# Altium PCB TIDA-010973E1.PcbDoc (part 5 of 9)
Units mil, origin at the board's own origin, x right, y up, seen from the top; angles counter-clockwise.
Board outline 5166 x 3669 mil, 8 copper layers (L01 - TOP, L02 - GND, L03 - SIG, L04 - GND, L05 - PWR, L06 - SIG, L07 - GND, L08 - BOTTOM), stack 61.7 mil thick; 677 components, 493 nets, 2522 pads, 1424 vias.
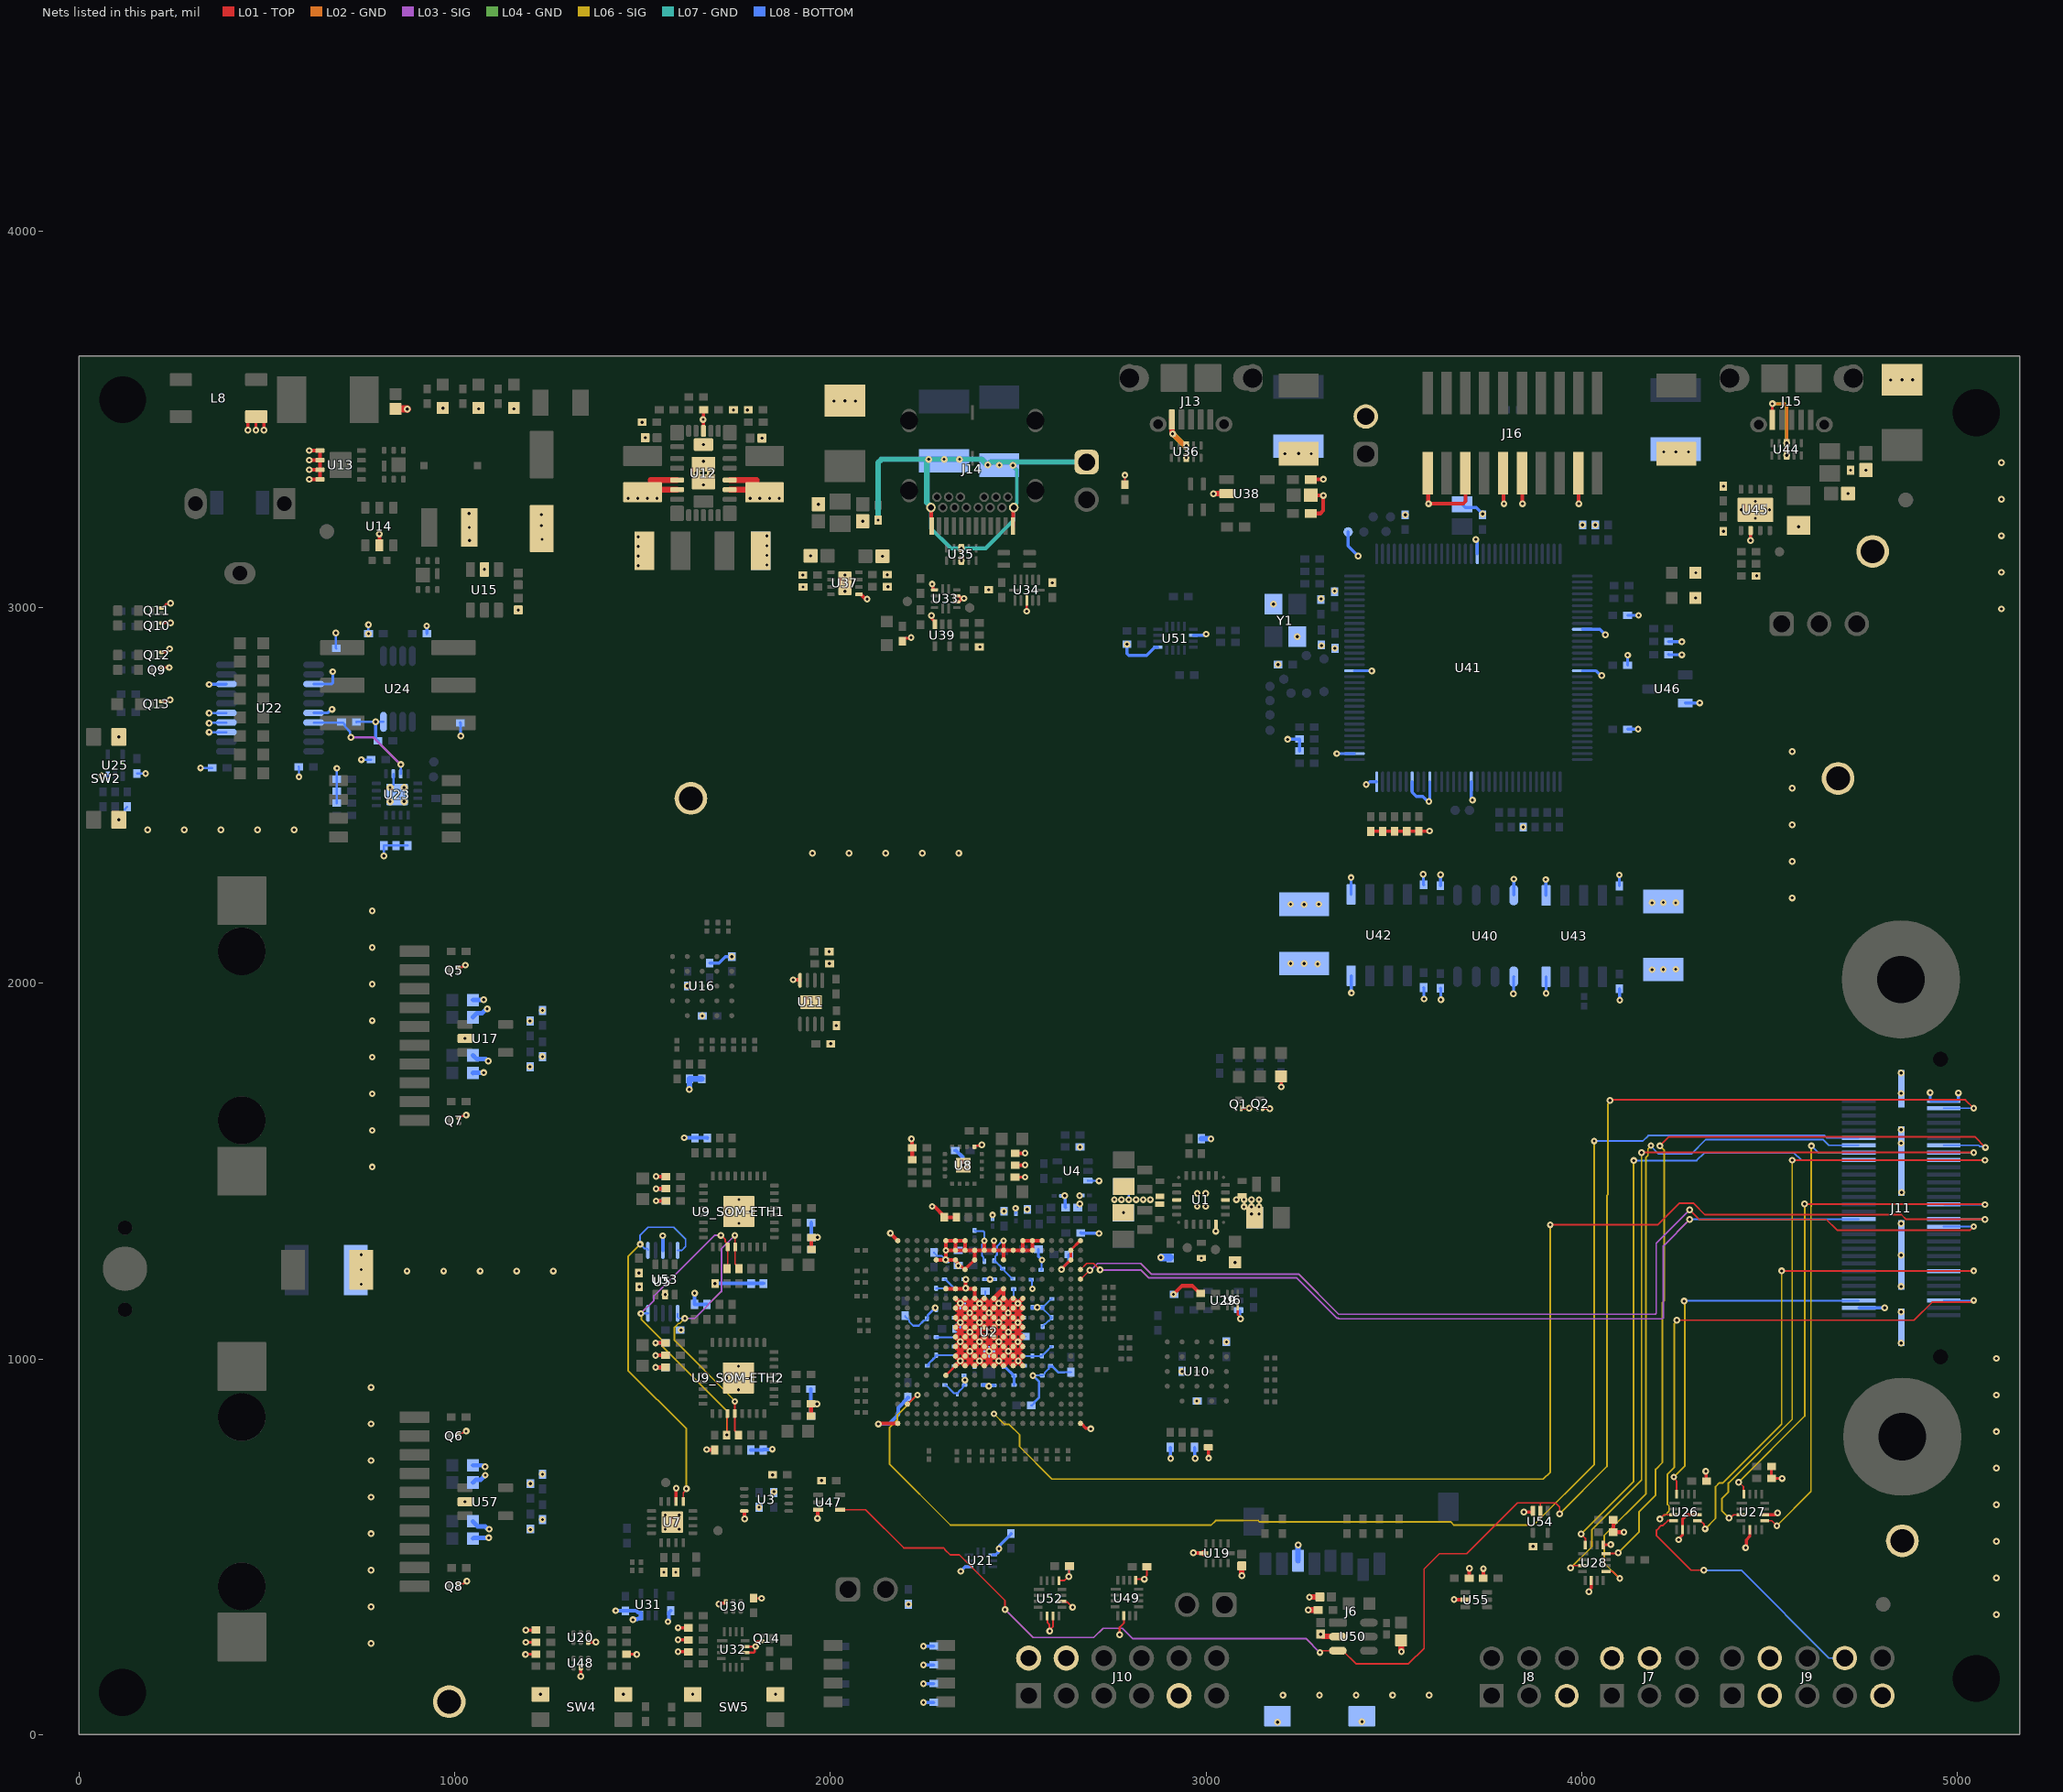
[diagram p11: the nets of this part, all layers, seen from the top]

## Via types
v1: diameter 18, hole 8, L01 - TOP to L08 - BOTTOM, tented both sides, 1389 vias
v2: diameter 19.68, hole 7.87, L01 - TOP to L08 - BOTTOM, 24 vias
v3: diameter 19.68, hole 7.87, L01 - TOP to L08 - BOTTOM, tented both sides, 11 vias

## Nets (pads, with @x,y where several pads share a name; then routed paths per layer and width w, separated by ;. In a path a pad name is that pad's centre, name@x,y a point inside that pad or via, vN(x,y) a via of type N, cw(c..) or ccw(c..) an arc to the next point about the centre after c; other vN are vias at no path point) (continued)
FSITX0_DATA1: J9.8 U26.4 | length 707.4
  L01 - TOP w4.5: U26.4@4244.5,569.38 4243.69,570.19 4229.25,570.19 4216.23,557.17 4211.77,557.17 4198.75,544.15 4198.75,529.85 4290.6,438 v1(4325,438)
  L08 - BOTTOM w4.5: v1(4325,438) 4325.5,437.5 4424.1,437.5 4657.6,204 J9.8@4700,204
GND: C1.1 C2.1 C3.1 C4.1 C5.1 C6.1 C7.1 C8.1 C9.1 C10.1 C11.1 C12.1 C13.1 C14.2 C15.2 C16.2 C17.1 C18.1 C19.1 C20.2 C21.2 C22.2 C23.2 C24.2 C25.2 C26.2 C27.1 C28.1 C29.1 C30.1 C31.1 C32.1 C33.1 C34.1 C35.2 C36.2 C37.2 C38.2 C39.2 C40.1 C41.1 C42.1 C43.2 C44.2 C45.1 C48.1 C49.2 C50.2 C51.2 C52.1 C53.1 C54.1 C55.1 C56.2 C57.2 C58.2 C59.1 C60.1 C61.2 C62.1 C63.2 C64.2 C65.2 C66.2 C67.2 C68.1 C69_SOM-ETH1.2 C69_SOM-ETH2.2 C70_SOM-ETH1.2 C70_SOM-ETH2.2 C71_SOM-ETH1.2 C71_SOM-ETH2.2 C72_SOM-ETH1.2 C72_SOM-ETH2.2 C73_SOM-ETH1.2 C73_SOM-ETH2.2 C74_SOM-ETH1.2 C74_SOM-ETH2.2 C75_SOM-ETH1.2 C75_SOM-ETH2.2 C76_SOM-ETH1.2 C76_SOM-ETH2.2 C77_SOM-ETH1.2 C77_SOM-ETH2.2 C78_SOM-ETH1.2 C78_SOM-ETH2.2 C79_SOM-ETH1.2 C79_SOM-ETH2.2 C80_SOM-ETH1.2 C80_SOM-ETH2.2 C81_SOM-ETH1.1 C81_SOM-ETH2.1 C82.2 C83.2 C84.2 C85.1 C86.2 C87.2 C88.1 C89.1 C90.1 C91.2 C92.1 C93.1 C94.1 C95.1 C96.2 C97.2 C100.2 C102.2 C103.2 C104.2 C105.2 C106.2 C107.2 C108.2 C109.2 C110.2 C111.2 C112.2 C113.2 C114.2 C115.2 C116.1 C117.2 C118.2 C119.2 C120.1 C121.1 C122.2 C123.1 C124.2 C125.1 C126.1 C127.2 C128.2 C129.2 C130.1 C131.1 C132.2 C133.2 C134.1 C135.1 C136.2 C137.2 C138.1 C145.2 C146.2 C147.2 C151.2 C172.1 C173.1 C174.1 C175.2 C176.1 C177.2 C178.2 C179.1 C180.2 C181.1 C182.2 C183.2 C184.2 C185.2 C186.2 C187.2 C188.2 C189.2 C190.1 C191_SOM-ETH1.2 C191_SOM-ETH2.2 C192.1 C193.1 C194.2 C195.2 C196.2 C197.2 C198.1 C199.1 C200.1 C201.1 C202.1 C203.1 C204.1 C205.1 C206.2 C207.1 C208.1 C209.2 C210.1 C211.1 C212.2 C213.1 C214.2 C215.1 C216.2 C217.1 C218.1 C219.2 D1.1 D4.1 D5.1 D6.1 D18.1 J6.6 J6.10 J7.2 J7.4 J8.5 J9.3 J9.4 J9.9 J10.2 J10.4 J10.9 J11.3 J11.60 J11.MP1 J11.MP2 J11.MP3 J11.MP4 J13.5 J14.A1 J14.A12 J14.B1 J14.B12 J16.4 J16.10 J16.12 J16.16 J16.20 J17.2 J20.1 L8.3 Q1.2 Q2.2 Q5.2 Q6.2 Q7.2 Q8.2 Q9.2 Q10.2 Q11.2 Q12.2 Q13.2 Q14.2 R2.1 R6.2 R14.2 R21.1 R25_SOM-ETH1.1 R25_SOM-ETH2.1 R26_SOM-ETH1.1 R26_SOM-ETH2.1 R28_SOM-ETH1.2 R28_SOM-ETH2.2 R51.1 R52.1 R56.1 R57.1 R59.1 R61.1 R62.1 R88.1 R93.1 R95.1 R96.1 R103.1 R108.2 R109.2 R110.2 R111.2 R114.1 R115.1 R116.1 R117.1 R118.1 R119.1 R128.1 R129.1 R130.1 R131.1 R132.1 R134.2 R139.1 R140.1 R142.2 R143.1 R144.2 R162.1 R169.1 R180.1 R181.2 R190.1 R191.1 R195.2 R197.2 R199.2 R200.2 R204_SOM-ETH1.2 R204_SOM-ETH2.2 R205_SOM-ETH1.2 R205_SOM-ETH2.2 R206_SOM-ETH1.2 R206_SOM-ETH2.2 SW2.1 SW2.3 SW4.1 SW4.3 SW5.1 SW5.3 TP2.1 TP3.1 TP4.1 TP5.1 U1.6 U1.10 U1.22 U2.A1 U2.A20 U2.F6 U2.F15 U2.G7 U2.G8 U2.G9 U2.G10 U2.G11 U2.G12 U2.G13 U2.G14 U2.H7 U2.H8 U2.H9 U2.H10 U2.H11 U2.H12 U2.H13 U2.H14 U2.J7 U2.J8 U2.J9 U2.J10 U2.J11 U2.J12 U2.J13 U2.J14 U2.K7 U2.K8 U2.K9 U2.K10 U2.K11 U2.K12 U2.K13 U2.K14 U2.L7 U2.L8 U2.L9 U2.L10 U2.L11 U2.L12 U2.L13 U2.L14 U2.M7 U2.M8 U2.M9 U2.M10 U2.M11 U2.M12 U2.M13 U2.M14 U2.N7 U2.N8 U2.N9 U2.N10 U2.N11 U2.N12 U2.N13 U2.N14 U2.P7 U2.P8 U2.P9 U2.P10 U2.P11 U2.P12 U2.P13 U2.P14 U2.R6 U2.R9 U2.R12 U2.R14 U2.R15 U2.U13 U2.V2 U2.V5 U2.V9 U2.V12 U2.V14 U2.V16 U2.W2 U2.W6 U2.W7 U2.W8 U2.W9 U2.W10 U2.W11 U2.W12 U2.W13 U2.W14 U2.W15 U2.Y1 U2.Y5 U2.Y6 U2.Y7 U2.Y9 U2.Y10 U2.Y11 U2.Y13 U2.Y14 U2.Y15 U2.Y20 U3.4 U4.3 U5.3 U6.3 U7.6 U7.17@1579.47,565.88 U8.1 U8.17 U9_SOM-ETH1.33 U9_SOM-ETH2.33 U10.B3 U10.C1 U10.E5 U11.4 U11.9 U12.5 U12.6 U12.16 U12.17 U12.24 U12.27 U12.28 U12.29 U13.5 U13.6 U13.7 U13.8 U14.2 U15.2 U16.B3 U16.C1 U16.E5 U17.2 U19.5 U20.3 U21.3 U21.8 U22.3 U22.4 U22.5 U22.8 U22.13 U22.16 U23.6 U23.17@847.12,2502.16 U24.4 U25.3 U26.6 U26.10 U27.6 U27.10 U28.6 U28.13 U29.3 U30.3 U31.3 U32.10 U32.11 U33.3 U33.10 U33.11 U34.9 U35.3@2349,3157.44 U35.8@2349,3124.56 U36.3@2947.31,3398.13 U36.8@2947.31,3431 U37.5 U37.9 U38.2 U39.3 U40.5 U42.4 U43.4 U47.3 U48.2 U49.6 U49.13 U50.2 U51.6 U51.13 U52.6 U52.7 U52.10 U52.13 U53.2 U54.3 U55.2 U57.2 | length 15938.3
  L01 - TOP w4.5: Q8.2@1011.02,401.89 1024.13,401.89 1031.24,409 v1(1033,409) ; Q6.2@1011.02,801.89 1012.37,803.23 1022.99,803.23 1027.75,808 v1(1031,808)
  L01 - TOP w5: U52.6@2577.13,315.76 2578.56,314.32 2578.56,297.95 2582.87,293.64 2582.87,277.13 v1(2584,276) 2584,279.52 2592.87,288.39 U52.7@2592.87,315.76 ; U52.13@2608.62,410.24 2622.42,410.24 2633.18,421 v1(2635,421) 2635,447.31 C197.2@2636.69,449 ; U52.10@2616.5,355.13 2617.93,353.69 2630.31,353.69 v1(2645,339) ; v1(2770,266) 2770,285.75 2781.13,296.87 U49.6@2781.13,316.76 ; R132.1@2784,3326.69 v1(2784,3352) ; U49.13@2812.62,411.24 2812.62,412.56 2814.06,414 v1(2836,414) 2836,417.52 2842.69,424.2 C196.2@2842.69,447 ; Q2.2@3150.39,1666.2 3150.49,1666.1 3169.4,1666.1 v1(3169.5,1666)
  L01 - TOP w6: Q13.2@219.9,2749.99 Q13.2@219.8,2749.89 235.64,2749.89 239.75,2754 v1(243,2754) ; Q9.2@220.01,2840.57 240.43,2840.57 v1(241,2840) ; Q12.2@220.01,2880.57 232.57,2880.57 v1(242,2890) ; Q10.2@220.01,2958.57 223.61,2958.57 223.83,2958.79 243.79,2958.79 v1(244,2959) ; Q11.2@220.01,2998.57 221.98,2998.57 232.11,3008.7 241.7,3008.7 v1(244,3011) ; Q5.2@1008.8,2040.89 1010.14,2042.23 1019.99,2042.23 1025.75,2048 v1(1029,2048) ; Q7.2@1011.8,1640.89 1014.27,1640.89 1020.09,1646.7 1028.7,1646.7 v1(1031,1649) ; U32.10@1773.36,218.78 1796.31,218.78 1799.09,221.55 1799.09,233.09 v1@1800.59,234.59 ; U32.11@1773.36,234.53 1773.43,234.59 v1@1800.59,234.59 ; C172.1@1796,363.68 1796.68,363 v1(1817,363) ; Q14.2@1818.2,249.11 1806.51,249.11 1803.3,245.89 1803.3,237.3 v1(1801,235) v1@1800.59,234.59 ; U2.F15@2307.59,956.46 U2.G14@2333.18,982.05 ; U8.1@2383.54,1564.79 2383.54,1565.2 2385.96,1567.62 2401.07,1567.62 v1(2403.37,1569.91) ; v1(2523,2990) U34.9@2523,3018.44 ; U6.3@3084.28,1140.79 3084.28,1117.97 3092,1110.25 v1(3092,1107)
  L01 - TOP w8: v1(450,3472) 450,3495.06 462.73,3507.79 L8.3@472.39,3507.79 ; v1(471.5,3472) 471.5,3506.89 L8.3@472.39,3507.79 ; v1(493,3472) 493,3495.06 480.27,3507.79 L8.3@472.39,3507.79 ; v1(1189,214) 1189.23,214.23 1216.32,214.23 C194.2@1216.55,214.46 ; v1(1189.65,278) 1189.89,278.23 1216,278.23 C192.1@1216.24,278.46 ; v1(1189.97,246) 1190.2,246.23 1216.32,246.23 C174.1@1216.55,246.46 ; v1(1336.24,155.46) U48.2@1336.24,178.65 ; U20.3@1355.92,246.65 1356.1,246.83 1375.83,246.83 v1(1376,247) ; C195.2@1457.92,214.46 1458.15,214.23 1484.8,214.23 v1(1485.03,214) ; U7.6@1589.32,621 1589.66,621.34 1589.66,655.66 v1(1590,656) ; v1(1595,221) 1595.17,220.83 1622.38,220.83 C124.2@1622.55,220.65 ; v1(1595,253) 1595.17,252.83 1622.38,252.83 C173.1@1622.55,252.65 ; v1(1595,284.81) 1595.17,284.64 1622.38,284.64 C122.2@1622.55,284.46 ; U12.24@1662.41,3469.86 1662.75,3470.2 1662.75,3525.31 R62.1@1663.09,3525.65 ; v1(1704,348) 1705.91,349.91 1720.27,349.91 1722.18,351.82 U30.3@1722.18,353.28 ; R143.1@2192.28,2910.31 2192.28,2912.24 2198.13,2918.09 2213.09,2918.09 v1(2215,2920) ; v1(2269,2978) 2270.91,2976.09 2270.91,2969.82 2278.32,2962.42 U39.3@2278.32,2955.13 ; v1(2271,3062) 2272.91,3060.09 2272.91,3046.69 2272.98,3046.62 U33.3@2277.47,3046.62 ; U33.10@2336.53,3015.13 2342.31,3015.13 2349.27,3022.09 2354.09,3022.09 v1(2356,3024) ; U33.11@2336.53,3030.87 2342.31,3030.87 v1@2347.27,3025.91 ; v1(2340.46,1248.48) 2342.38,1246.57 2348.59,1246.57 2357.21,1237.95 U2.U13@2358.77,1237.95 U2.V12@2384.36,1263.54 ; C68.1@2491.62,1484.2 2491.77,1484.06 2518.22,1484.06 v1(2518.37,1483.91) ; v1(2615,1238) 2615,1239.41 2639.13,1263.54 U2.V2@2640.27,1263.54 U2.W2@2640.27,1289.13 2640.27,1290.26 2664.73,1314.72 U2.Y1@2665.86,1314.72 ; U2.A1@2665.86,828.5 2667.39,828.5 2679.98,815.91 2691.09,815.91 v1(2693,814) ; C85.1@3005.8,764.94 3006.4,764.34 3006.4,736.6 v1(3007,736) ; v1(3026,1340) 3026.07,1340.07 3026.07,1358.39 U1.6@3026.13,1358.46 ; Q1.2@3093.39,1666.7 3114.2,1666.7 v1(3114.5,1667) ; v1(3200,1723.94) D1.1@3200,1751.5 ; v1(3846,593) 3868.12,593 3870.03,594.91 U54.3@3870.03,595.88 ; C211.1@3870.03,501.29 v1(3870.31,501) ; v1(4019,381) 4019,383.71 4025.13,389.83 U28.6@4025.13,410.76 ; U28.13@4056.62,505.24 4057,505.62 4076.62,505.62 v1(4077,506) ; v1(4258,519) 4258,521.49 4268.06,531.55 4268.06,545.69 U26.6@4268.13,545.76 ; U26.6@4268.13,553.57 4268.13,574.13 4279.13,585.13 U26.10@4307.5,585.13 ; v1(4330,701) 4330.84,700.16 4330.84,675.84 C117.2@4331.69,675 ; v1(4436,498) 4437.91,499.91 4437.91,518.62 4447.06,527.77 4447.06,545.69 U27.6@4447.13,545.76 ; U27.10@4486.5,585.13 4513.42,585.13 4518.29,590 v1(4521,590) ; R118.1@4504.69,714 C118.2@4504.69,682 v1(4533,682)
  L01 - TOP w10: v1(613.19,3340.81) 641.69,3340.81 U13.8@641.88,3340.61 U13.7@641.88,3366.2 ; v1(613.19,3366.4) 641.69,3366.4 U13.7@641.88,3366.2 ; v1(613.19,3391.99) 641.69,3391.99 U13.6@641.88,3391.8 ; v1(613.19,3417.58) 641.69,3417.58 U13.5@641.88,3417.39 U13.6@641.88,3391.8 ; U14.2@800,3165.12 v1(800,3195.63) ; v1(1535.26,977.65) C74_SOM-ETH2.2@1561.45,977.68 ; v1(1535.26,1009.65) 1535.51,1009.91 1561.2,1009.91 C73_SOM-ETH2.2@1561.45,1010.16 ; v1@1535.27,1042.65 C81_SOM-ETH2.1@1561.45,1042.64 ; v1(1536.26,1420.65) C74_SOM-ETH1.2@1562.45,1420.68 ; v1(1536.26,1452.65) 1536.51,1452.91 1562.2,1452.91 C73_SOM-ETH1.2@1562.45,1453.16 ; v1@1536.27,1485.65 C81_SOM-ETH1.1@1562.45,1485.64 ; v1(1671,759) 1671.52,758.48 1691.61,758.48 R26_SOM-ETH2.1@1692.13,757.95 ; U3.4@1771.07,595.47 1771.44,595.47 1771.52,595.39 1771.52,574.97 v1(1771.98,574.52) ; v1(1901,2009) 1919.22,2009 1919.45,2008.77 U11.4@1919.45,2007.58 ; C70_SOM-ETH2.2@1948.82,847.99 C69_SOM-ETH2.2@1948.82,880.47 v1(1964.57,880.47) ; C70_SOM-ETH1.2@1949.82,1290.99 C69_SOM-ETH1.2@1949.82,1323.47 v1(1965.57,1323.47) ; v1(1966,576) 1966.89,576.89 1966.89,597.87 U47.3@1967.77,598.76 ; v1(1997.17,2083.83) R57.1@1997.5,2083.5 ; R56.1@1997.5,2052.5 R56.1@1998,2052 ; U37.5@2076.4,3034.76 2081.17,3034.76 2092.39,3023.53 2096.47,3023.53 v1(2098,3022) ; v1(2128,827) 2129.5,828.5 U2.A20@2179.64,828.5 ; v1(2159.95,1334.41) U2.Y20@2179.64,1314.72 ; v1(2216,1586) 2217.02,1584.98 2217.02,1562.93 C65.2@2218.03,1561.91 R199.2@2218.03,1530.42 ; J14.B1@2267.76,3265.85 2268.83,3264.79 2268.83,3217.54 J14.A12@2269.73,3216.64 ; v1(2271,1406) 2272.53,1404.47 2278.41,1404.47 2303.37,1379.51 2303.37,1376.75 2334.48,1376.75 C66.2@2335.23,1377.5 ; U2.V16@2282,1263.54 2282.13,1263.68 2306.87,1263.68 v1(2307,1263.81) ; U2.R15@2307.59,1186.77 U2.R14@2333.18,1186.77 v1@2358.77,1186.77 ; U2.Y14@2333.14,1314.65 U2.Y14@2333.18,1314.72 ; v1(2340.46,1248.48) 2337.98,1250.97 2337.98,1256.37 2333.18,1261.17 U2.V14@2333.18,1263.54 2333.05,1263.68 2307.13,1263.68 v1(2307,1263.81) ; v1(2360.8,1211.57) 2359.57,1210.35 2359.57,1187.57 v1@2358.77,1186.77 ; U2.P12@2384.36,1161.18 U2.R12@2384.36,1186.77 v1@2358.77,1186.77 ; U2.V12@2384.36,1263.54 U2.W12@2384.36,1289.13 ; v1(2409.95,1314.72) U2.W11@2409.95,1289.13 ; v1(2435.54,1314.72) U2.W10@2435.54,1289.13 ; U2.P9@2461.13,1161.18 U2.R9@2461.13,1186.77 ; U2.V9@2461.13,1263.54 U2.W9@2461.13,1289.13 ; v1(2461.13,1314.72) U2.W9@2461.13,1289.13 ; J14.A1@2486.27,3216.64 2487.17,3217.54 2487.17,3264.79 J14.B12@2488.24,3265.85 ; C67.2@2491.9,1516.03 2491.96,1515.97 2518.31,1515.97 v1(2518.37,1515.91) ; C64.2@2491.9,1547.53 2492.09,1547.72 2518.18,1547.72 v1(2518.37,1547.91) ; U2.Y5@2563.5,1314.72 U2.Y6@2537.91,1314.72 ; v1(2913.35,1172) 2936,1194.65 2963.38,1194.65 2984.03,1174 C62.1@2986,1174 ; v1@2966.5,483.5 U19.5@2993.07,483.5 ; R142.2@3278.62,3250 3304.21,3250 3312,3257.79 v1(3312,3298) 3279.67,3298 C135.1@3278.67,3299 ; C136.2@3278.62,3340 3279.12,3340.5 3311.5,3340.5 v1(3312,3341) ; J16.20@3590.43,3357.28 3591.22,3356.5 3591.22,3276.78 v1(3592,3276) 3684.58,3276 3690.43,3281.86 J16.16@3690.43,3357.28 ; v1(3660,360) 3660.34,359.66 3689.41,359.66 U55.2@3689.76,359.32 ; C218.1@3700.39,416.32 3700.69,416.62 3700.69,442.69 v1(3701,443) ; C219.2@3737.7,416.32 3738,416.61 v1(3738,442) ; J16.12@3790.43,3357.28 3791.72,3356 3791.72,3277.28 v1(3793,3276) ; J16.10@3840.43,3357.28 3841.22,3356.5 3841.22,3276.78 v1(3842,3276) ; J16.4@3990.43,3357.28 3991.22,3356.5 3991.22,3276.78 v1(3992,3276) ; R119.1@4083.69,572 C119.2@4083.69,539 v1(4112,539) ; U13.7@641.88,3366.2 U13.6@641.88,3391.8 ; v1(2307,1263.81) 2307.3,1264.11 2307.3,1288.84 v1(2307.59,1289.13) ; v1(2307.59,1289.13) 2307.66,1289.21 2307.66,1314.65 2333.11,1314.65 U2.Y14@2333.18,1314.72 ; v1(2307.59,1289.13) U2.W14@2333.18,1289.13 ; U2.W14@2333.18,1289.13 U2.Y14@2333.18,1314.72 ; U2.W14@2333.18,1289.13 U2.W13@2358.77,1289.13 ; U2.Y14@2333.18,1314.72 U2.Y14@2333.18,1314.72 ; U2.Y14@2333.18,1314.72 U2.Y13@2358.77,1314.72 U2.W13@2358.77,1289.13 ; U2.W13@2358.77,1289.13 U2.W12@2384.36,1289.13 ; U2.W12@2384.36,1289.13 U2.W11@2409.95,1289.13 ; U2.W11@2409.95,1289.13 U2.W10@2435.54,1289.13 ; U2.W10@2435.54,1289.13 U2.W9@2461.13,1289.13 ; U2.W9@2461.13,1289.13 U2.W8@2486.72,1289.13 U2.W7@2512.31,1289.13 ; U2.W7@2512.31,1289.13 U2.Y7@2512.31,1314.72 U2.Y6@2537.91,1314.72 ; U2.W7@2512.31,1289.13 U2.W6@2537.91,1289.13 U2.Y6@2537.91,1314.72
  L01 - TOP w12: U2.G14@2333.18,982.05 v1@2345.98,994.84 ; U2.P14@2333.18,1161.18 v1@2345.98,1148.39 ; v1@2448.31,1148.42 U2.P10@2435.54,1161.18 ; U2.R9@2461.13,1186.77 U2.P10@2435.54,1161.18 ; v1@2473.94,1020.42 U2.H8@2486.72,1007.64 ; U2.G7@2512.31,982.05 2500.02,994.35 2499.52,994.84 U2.H8@2486.72,1007.64 ; U2.P7@2512.31,1161.18 v1@2499.52,1148.39 ; v1@2345.98,994.84 U2.H13@2358.77,1007.64 ; v1@2345.98,994.84 2346.24,994.57 U2.G13@2358.77,982.05 2371.57,994.84 ; v1@2345.98,994.84 U2.H14@2333.18,1007.64 2345.98,1020.43 ; 2345.98,1020.43 U2.H13@2358.77,1007.64 ; 2345.98,1020.43 U2.J14@2333.18,1033.23 v1@2345.98,1046.02 ; 2345.98,1020.43 U2.J13@2358.77,1033.23 ; v1@2345.98,1046.02 U2.J13@2358.77,1033.23 ; v1@2345.98,1046.02 U2.K13@2358.77,1058.82 ; v1@2345.98,1046.02 U2.K14@2333.18,1058.82 2345.98,1071.61 ; 2345.98,1071.61 U2.L13@2358.77,1084.41 ; 2345.98,1071.61 U2.K13@2358.77,1058.82 ; 2345.98,1071.61 U2.L14@2333.18,1084.41 v1@2345.98,1097.2 ; v1@2345.98,1097.2 U2.M13@2358.77,1110 ; v1@2345.98,1097.2 v1(2346.15,1097.15) U2.L13@2358.77,1084.41 ; v1@2345.98,1097.2 U2.M14@2333.18,1110 2345.98,1122.8 ; 2345.98,1122.8 U2.M13@2358.77,1110 ; 2345.98,1122.8 U2.N13@2358.77,1135.59 ; 2345.98,1122.8 U2.N14@2333.18,1135.59 v1@2345.98,1148.39 ; v1@2345.98,1148.39 2346.02,1148.35 U2.N13@2358.77,1135.59 ; v1@2345.98,1148.39 U2.P13@2358.77,1161.18 2371.57,1148.39 ; U2.H13@2358.77,1007.64 2371.57,994.84 ; U2.H13@2358.77,1007.64 v1@2371.57,1020.43 ; U2.J13@2358.77,1033.23 v1@2371.57,1020.43 ; U2.J13@2358.77,1033.23 2371.57,1046.02 ; U2.K13@2358.77,1058.82 v1@2371.57,1071.61 ; U2.K13@2358.77,1058.82 2371.57,1046.02 ; U2.L13@2358.77,1084.41 v1@2371.57,1071.61 ; U2.L13@2358.77,1084.41 2371.57,1097.2 ; U2.M13@2358.77,1110 v1@2371.57,1122.8 ; U2.M13@2358.77,1110 2371.57,1097.2 ; U2.N13@2358.77,1135.59 2371.32,1123.04 v1@2371.57,1122.8 ; U2.N13@2358.77,1135.59 2371.57,1148.39 ; 2371.57,994.84 U2.G12@2384.36,982.05 v1@2397.16,994.84 ; 2371.57,994.84 U2.H12@2384.36,1007.64 ; v1@2371.57,1020.43 U2.J12@2384.36,1033.23 ; v1@2371.57,1020.43 2371.68,1020.32 U2.H12@2384.36,1007.64 ; 2371.57,1046.02 U2.J12@2384.36,1033.23 ; 2371.57,1046.02 U2.K12@2384.36,1058.82 ; v1@2371.57,1071.61 U2.K12@2384.36,1058.82 ; v1@2371.57,1071.61 U2.L12@2384.36,1084.41 ; 2371.57,1097.2 U2.M12@2384.36,1110 ; 2371.57,1097.2 U2.L12@2384.36,1084.41 ; v1@2371.57,1122.8 U2.M12@2384.36,1110 ; v1@2371.57,1122.8 U2.N12@2384.36,1135.59 ; 2371.57,1148.39 U2.N12@2384.36,1135.59 ; 2371.57,1148.39 U2.P12@2384.36,1161.18 v1@2397.16,1148.39 ; U2.H12@2384.36,1007.64 v1@2397.16,994.84 ; U2.H12@2384.36,1007.64 2397.16,1020.43 ; U2.J12@2384.36,1033.23 v1@2397.16,1046.02 ; U2.J12@2384.36,1033.23 2397.16,1020.43 ; U2.K12@2384.36,1058.82 v1@2397.16,1046.02 ; U2.K12@2384.36,1058.82 2397.16,1071.61 ; U2.L12@2384.36,1084.41 v1@2397.16,1097.2 ; U2.L12@2384.36,1084.41 2397.16,1071.61 ; U2.M12@2384.36,1110 2397.16,1122.8 ; U2.M12@2384.36,1110 v1@2397.16,1097.2 ; U2.N12@2384.36,1135.59 v1@2397.16,1148.39 ; U2.N12@2384.36,1135.59 2397.16,1122.8 ; v1@2397.16,994.84 U2.G11@2409.95,982.05 2422.75,994.84 ; v1@2397.16,994.84 U2.H11@2409.95,1007.64 ; 2397.16,1020.43 U2.J11@2409.95,1033.23 ; 2397.16,1020.43 U2.H11@2409.95,1007.64 ; v1@2397.16,1046.02 U2.K11@2409.95,1058.82 ; v1@2397.16,1046.02 2397.31,1045.87 U2.J11@2409.95,1033.23 ; 2397.16,1071.61 U2.L11@2409.95,1084.41 ; 2397.16,1071.61 U2.K11@2409.95,1058.82 ; v1@2397.16,1097.2 2397.46,1096.9 U2.L11@2409.95,1084.41 ; v1@2397.16,1097.2 U2.M11@2409.95,1110 ; 2397.16,1122.8 U2.M11@2409.95,1110 ; 2397.16,1122.8 U2.N11@2409.95,1135.59 ; v1@2397.16,1148.39 U2.P11@2409.95,1161.18 2422.75,1148.39 ; v1@2397.16,1148.39 2397.31,1148.23 U2.N11@2409.95,1135.59 ; U2.H11@2409.95,1007.64 v1@2422.75,1020.43 ; U2.H11@2409.95,1007.64 2422.75,994.84 ; U2.J11@2409.95,1033.23 v1@2422.75,1020.43 ; U2.J11@2409.95,1033.23 2422.75,1046.02 ; U2.K11@2409.95,1058.82 2422.75,1046.02 ; U2.K11@2409.95,1058.82 v1@2422.75,1071.61 ; U2.L11@2409.95,1084.41 2422.75,1097.2 ; U2.L11@2409.95,1084.41 v1@2422.75,1071.61 ; U2.M11@2409.95,1110 v1@2422.75,1122.8 ; U2.M11@2409.95,1110 2422.75,1097.2 ; U2.N11@2409.95,1135.59 v1@2422.75,1122.8 ; U2.N11@2409.95,1135.59 2422.75,1148.39 ; 2422.75,994.84 U2.H10@2435.54,1007.64 ; 2422.75,994.84 U2.G10@2435.54,982.05 v1@2448.34,994.84 ; v1@2422.75,1020.43 U2.J10@2435.54,1033.23 ; v1@2422.75,1020.43 U2.H10@2435.54,1007.64 ; 2422.75,1046.02 U2.J10@2435.54,1033.23 ; 2422.75,1046.02 U2.K10@2435.54,1058.82 ; v1@2422.75,1071.61 U2.K10@2435.54,1058.82 ; v1@2422.75,1071.61 U2.L10@2435.54,1084.41 ; 2422.75,1097.2 U2.L10@2435.54,1084.41 ; 2422.75,1097.2 U2.M10@2435.54,1110 ; v1@2422.75,1122.8 U2.M10@2435.54,1110 ; v1@2422.75,1122.8 U2.N10@2435.54,1135.59 ; 2422.75,1148.39 U2.P10@2435.54,1161.18 ; 2422.75,1148.39 U2.N10@2435.54,1135.59 ; U2.H10@2435.54,1007.64 2448.34,1020.43 ; U2.H10@2435.54,1007.64 v1@2448.34,994.84 ; U2.J10@2435.54,1033.23 v1@2448.34,1046.02 ; U2.J10@2435.54,1033.23 2448.34,1020.43 ; U2.K10@2435.54,1058.82 v1@2448.34,1046.02 ; U2.K10@2435.54,1058.82 2448.34,1071.61 ; U2.L10@2435.54,1084.41 v1@2448.34,1097.2 ; U2.L10@2435.54,1084.41 2448.34,1071.61 ; U2.M10@2435.54,1110 2448.34,1122.8 ; U2.M10@2435.54,1110 v1@2448.34,1097.2 ; U2.N10@2435.54,1135.59 v1@2448.34,1148.39 ; U2.N10@2435.54,1135.59 2448.34,1122.8 ; v1@2448.34,994.84 U2.H9@2461.13,1007.64 ; v1@2448.34,994.84 2448.4,994.78 U2.G9@2461.13,982.05 2473.93,994.84 ; 2448.34,1020.43 U2.J9@2461.13,1033.23 ; 2448.34,1020.43 U2.H9@2461.13,1007.64 ; v1@2448.34,1046.02 2448.42,1045.94 U2.J9@2461.13,1033.23 ; v1@2448.34,1046.02 U2.K9@2461.13,1058.82 ; 2448.34,1071.61 U2.K9@2461.13,1058.82 ; 2448.34,1071.61 U2.L9@2461.13,1084.41 ; v1@2448.34,1097.2 U2.M9@2461.13,1110 ; v1@2448.34,1097.2 2448.55,1096.99 U2.L9@2461.13,1084.41 ; 2448.34,1122.8 U2.N9@2461.13,1135.59 ; 2448.34,1122.8 U2.M9@2461.13,1110 ; v1@2448.34,1148.39 U2.P9@2461.13,1161.18 2473.93,1148.39 ; v1@2448.34,1148.39 U2.N9@2461.13,1135.59 ; U2.H9@2461.13,1007.64 v1@2473.93,1020.43 ; U2.H9@2461.13,1007.64 2473.93,994.84 ; U2.J9@2461.13,1033.23 v1@2473.93,1020.43 ; U2.J9@2461.13,1033.23 2473.93,1046.02 ; U2.K9@2461.13,1058.82 v1@2473.93,1071.61 ; U2.K9@2461.13,1058.82 2473.93,1046.02 ; U2.L9@2461.13,1084.41 v1@2473.93,1071.61 ; U2.L9@2461.13,1084.41 2473.93,1097.2 ; U2.M9@2461.13,1110 v1@2473.93,1122.8 ; U2.M9@2461.13,1110 2473.93,1097.2 ; U2.N9@2461.13,1135.59 2473.93,1148.39 ; U2.N9@2461.13,1135.59 2473.72,1123.01 v1@2473.93,1122.8 ; 2473.93,994.84 U2.H8@2486.72,1007.64 ; 2473.93,994.84 U2.G8@2486.72,982.05 U2.H7@2512.31,1007.64 2499.52,1020.43 ; v1@2473.93,1020.43 U2.J8@2486.72,1033.23 ; 2473.93,1046.02 U2.K8@2486.72,1058.82 ; 2473.93,1046.02 U2.J8@2486.72,1033.23 ; v1@2473.93,1071.61 U2.K8@2486.72,1058.82 ; v1@2473.93,1071.61 U2.L8@2486.72,1084.41 ; 2473.93,1097.2 U2.M8@2486.72,1110 ; 2473.93,1097.2 U2.L8@2486.72,1084.41 ; v1@2473.93,1122.8 U2.M8@2486.72,1110 ; v1@2473.93,1122.8 U2.N8@2486.72,1135.59 ; 2473.93,1148.39 U2.N8@2486.72,1135.59 ; 2473.93,1148.39 U2.P8@2486.72,1161.18 v1@2499.52,1148.39 ; U2.H8@2486.72,1007.64 2499.52,1020.43 ; U2.J8@2486.72,1033.23 v1@2499.52,1046.02 ; U2.J8@2486.72,1033.23 2499.52,1020.43 ; U2.K8@2486.72,1058.82 v1@2499.52,1046.02 ; U2.K8@2486.72,1058.82 2499.52,1071.61 ; U2.L8@2486.72,1084.41 v1@2499.52,1097.2 ; U2.L8@2486.72,1084.41 2499.52,1071.61 ; U2.M8@2486.72,1110 v1@2499.52,1097.2 ; U2.M8@2486.72,1110 2499.52,1122.8 ; U2.N8@2486.72,1135.59 v1@2499.52,1148.39 ; U2.N8@2486.72,1135.59 2499.52,1122.8 ; 2499.52,1020.43 U2.J7@2512.31,1033.23 2499.61,1045.94 v1@2499.52,1046.02 ; v1@2499.52,1046.02 U2.K7@2512.31,1058.82 2499.52,1071.61 ; 2499.52,1071.61 U2.L7@2512.31,1084.41 2499.61,1097.12 v1@2499.52,1097.2 ; v1@2499.52,1097.2 U2.M7@2512.31,1110 2499.52,1122.8 ; 2499.52,1122.8 U2.N7@2512.31,1135.59 2499.61,1148.3 v1@2499.52,1148.39
  L01 - TOP w15: v1(1513.33,3290) 1521.79,3298.45 C94.1@1521.79,3313.36 ; U12.6@1592.53,3313.36 C94.1@1521.79,3313.36 ; U12.5@1592.53,3338.95 1521.79,3338.95 C94.1@1521.79,3313.36 ; U12.16@1732.29,3313.36 C95.1@1803.88,3313.36 ; U12.17@1732.29,3338.95 1803.88,3338.95 C95.1@1803.88,3313.36 ; v1(1812.67,3290) 1803.88,3298.79 C95.1@1803.88,3313.36 ; J13.5@2908.82,3500.07 2909.19,3499.7 2909.19,3464.62 2911,3462.81 v1(2911,3462) ; v1(2966,484) v1@2966.5,483.5 ; U19.5@2993.07,483.5 U19.5@2993.57,483 ; v1(3019.81,3302.34) 3020.14,3302.67 3054.54,3302.67 U38.2@3054.87,3303 ; v1(3095,423) C193.1@3095,449.24 ; v1(3272,332) C179.1@3298.32,332 ; v1(3275,366) 3275.5,366.5 3302.19,366.5 C182.2@3302.69,367 ; v1(3305,267.69) 3305,267.25 3310.13,262.12 3349.52,262.12 U50.2@3350.64,261 ; C181.1@3519,251.31 3519.5,250.81 3519.5,221.5 v1(3520,221)
  L01 - TOP w20: C97.2@843,3528.31 843.15,3528.15 873.85,3528.15 v1(874,3528)
  L04 - GND w15: v1(2911,3462) 2941.43,3431.57 2946.74,3431.57 v1(2947.31,3431)
  L02 - GND w15: v1(2911,3462) 2941.43,3431.57 2946.74,3431.57 v1(2947.31,3431)
  L07 - GND w10: J14.B1@2267.76,3265.85 2267.76,3210.95 2321.28,3157.44 v1(2349,3157.44) 2413.72,3157.44 2488.24,3231.95 J14.B12@2488.24,3265.85 2488.24,3270.07 2496.28,3278.12 2496.28,3365.55 2486,3375.84 v1(2486,3378)
  L07 - GND w15: v1(2127.32,3232.31) 2127.32,3385.41 2136.1,3394.2 v1(2262,3394.2) ; J14.B1@2267.76,3265.85 2267.76,3268.72 2257.22,3279.26 2257.22,3388.6 2262,3393.39 v1(2262,3394.2) ; J20.1@2682,3387 2427.81,3387 2419.81,3379 v1(2419,3379) 2418.19,3379 2402.99,3394.2 v1(2344,3394.2) v1(2303,3394.2) v1(2262,3394.2) ; v1(2911,3462) 2941.43,3431.57 2946.74,3431.57 v1(2947.31,3431)
  L08 - BOTTOM w4.3: C48.1@2458.92,1240.32 2460.72,1240.32 2463.74,1237.3 2463.74,1233.94 2484.05,1213.64 C28.1@2485.84,1213.64
  L08 - BOTTOM w4.5: C199.1@2589,1108.2 C199.1@2589,1110 2589,1111.8 2586.08,1114.72 2584.48,1114.72 2564,1135.2 2564,1136.83 C190.1@2564,1137 2564,1138.8 2566.92,1141.72 2569.91,1141.72 2588.19,1160 C60.1@2589.99,1160
  L08 - BOTTOM w5: C39.2@2199.3,1115.31 2199.3,1113.35 2210.6,1102.05 2210.6,1098.79 2220.79,1088.6 2235.21,1088.6 2249.14,1102.53 2254.33,1102.53 2257,1105.2 C204.1@2257,1107 ; C216.2@2276.15,1283.85 2276.15,1281.88 2283.49,1274.54 2296.27,1274.54 v1(2307,1263.81) C217.1@2307,1260.21 ; C34.1@2281.61,1188.13 2281.89,1187.85 2307.09,1187.85 C8.1@2307.36,1187.58 ; C32.1@2282,1010 2330.63,1010 v1(2346.15,994.48) 2345.28,994.48 2331.8,981 C6.1@2330,981 ; C53.1@2282,1058 2333.96,1058 v1(2346.15,1045.81) 2344.61,1045.81 2331.8,1033 C12.1@2330,1033 ; C19.1@2305.01,931 2306.81,931 2328.41,909.41 2336.37,909.41 C41.1@2338,907.77 ; v1(2307.59,1289.13) C214.2@2340.46,1289.13 ; C10.1@2330,1110 2331.8,1110 2344.65,1097.15 v1(2346.15,1097.15) ; C51.2@2333.12,1255.82 v1(2340.46,1248.48) ; C41.1@2338,906 C41.1@2338,907.77 ; C7.1@2356,956 2356.82,955.18 2356.82,931.68 C202.1@2357.63,930.87 2355.84,930.87 2353.16,928.19 2353.16,924.28 2341.37,912.48 2341.37,911.14 C41.1@2338,907.77 ; C2.1@2384,980.01 2384,981.81 2396.67,994.48 v1(2397.48,994.48) ; C215.1@2384,1342.14 2385.68,1340.47 2407.02,1340.47 2409.95,1337.54 v1(2409.95,1314.72) 2409.95,1311.21 2404.07,1305.32 2404.07,1274.49 2407.33,1271.23 2407.33,1262.67 C42.1@2409.26,1260.74 ; v1(2396.92,1147.84) 2412.31,1163.24 C36.2@2412.31,1181 ; v1(2432,1383) 2432,1373.64 C213.1@2432.15,1373.49 ; C201.1@2435.5,929.5 C201.1@2437,931 ; C48.1@2458.61,1237.45 2456.81,1237.45 2454.13,1240.12 2454.13,1245.1 2442.41,1256.83 2438.82,1256.83 2436.15,1259.5 C45.1@2436.15,1261.3 2438.82,1263.97 2438.82,1272.75 2443.44,1277.37 2443.44,1299.51 2458.65,1314.72 v1(2461.13,1314.72) ; C1.1@2488,1186 2488,1160.03 2499.15,1148.88 v1(2499.15,1147.84) ; v1(2493,1401) 2493.57,1400.43 2493.57,1388.05 C52.1@2494.15,1387.48 ; v1(2499.15,1096.66) 2499.15,1096.95 2512.2,1110 C11.1@2514,1110 ; v1@2505.31,1047.97 2517.35,1060 C38.2@2519.31,1060 ; C13.1@2516,982 2514.2,982 2501.72,994.48 v1(2500.15,994.48) 2513.67,1008 C5.1@2538,1008 C33.1@2563,1008 2563,1009.8 2565.67,1012.47 2567.54,1012.47 2580.9,1025.83 2580.9,1026.33 2587.23,1032.66 C40.1@2589,1032.66 ; C209.2@2530.5,1213.67 2533.18,1211 C209.2@2534.98,1211 2536.44,1209.53 2536.44,1188.24 v1(2537.91,1186.77) ; v1(2539,956) C203.1@2563.99,956 2565.79,956 2570.6,960.82 2570.6,962.69 2581.53,973.61 2581.53,979.33 C30.1@2584.2,982 ; C200.1@2561,1237 2562.25,1238.25 2562.25,1262.3 v1(2563.5,1263.54) ; C17.1@2565,1086 2565,1087.8 2569.8,1092.6 2571.67,1092.6 2580.88,1101.81 2582.61,1101.81 C199.1@2589,1108.2 ; v1(2635,421) 2635,447.32 R180.1@2636.68,449 ; C57.2@2658.31,1403 2658.31,1407.31 v1(2664,1413) ; C189.2@2780.8,1459.1 2794.4,1445.51 v1(2794.4,1424)
  L08 - BOTTOM w6: v1(61,2552) 76.18,2552 U25.3@77.32,2550.87 ; v1(106.46,2434.76) 121.97,2450.27 121.97,2462.69 C114.2@128.81,2469.54 ; C116.1@155,2558.32 155.32,2558 v1(178,2558) ; v1(324,2573) R96.1@355.32,2573 ; v1(347,2692) 347.82,2692.82 391.97,2692.82 U22.4@392.8,2693.65 ; v1(347,2719) 347.12,2719.12 392.68,2719.12 U22.5@392.8,2719.24 ; v1(347,2668) U22.3@392.77,2668.03 ; C112.2@585.31,2576 586,2575.31 v1(586,2549) ; v1(684,2932) 684,2892.31 R114.1@685.32,2891 ; R108.2@686.63,2479 687,2479.37 v1(687,2572) ; R95.1@738.68,2695 739.68,2696 v1(790,2696) 810.33,2696 U24.4@810.93,2695.4 ; v1(752,2595) R111.2@777.63,2595 ; v1(771,2930) v1(771,2954) ; v1(812,2339) R103.1@812,2366.32 C113.2@876,2366.31 ; v2(828.42,2520.86) 830.43,2520.86 837.28,2527.7 U23.6@837.28,2557.28 ; C204.1@2257,1107 2259.17,1109.17 2259.17,1116.13 v1(2279.38,1136.33) ; C198.1@2257.99,982 2259.79,982 2261.96,984.17 2261.96,987.87 2274.31,1000.22 2274.31,1000.51 2282,1008.2 C32.1@2282,1010 ; C205.1@2304,1212 2305.8,1212 2328.89,1188.91 2328.89,1187.88 ; C8.1@2307.36,1187.58 C8.1@2307.66,1187.88 ; C8.1@2308.18,1188.4 C8.1@2307.66,1187.88 ; v1(2360.18,1188.18) 2359.88,1187.88 2328.89,1187.88 ; C14.2@2535.13,876.55 2537.1,876.55 2543.94,883.4 2543.94,886 2555.81,897.86 2555.81,939.19 v1(2539,956) ; C30.1@2584.2,982 2586.37,979.83 2591.58,979.83 2607.26,964.15 2622.09,964.15 2622.82,964.88 C49.2@2640.37,964.88 ; U4.3@2685.35,1474.41 2685.56,1474.2 2714.8,1474.2 v1(2715,1474) ; C8.1@2307.66,1187.88 2328.89,1187.88
  L08 - BOTTOM w8: v1(347,2795) 347.51,2795.51 392.29,2795.51 U22.8@392.8,2796.01 ; U22.16@625.08,2719.24 661.64,2719.24 671.4,2729 v1(674,2729) ; U22.13@625.08,2796.01 672.49,2796.01 676,2799.53 v1(676,2829) ; v1(790,2696) 790,2650.84 795.84,2645 R116.1@796.32,2645 R116.1@798.28,2645 ; v1(926,2951) 926.34,2950.66 926.34,2930.34 C115.2@926.69,2930 ; R115.1@1015.68,2693 1016.34,2692.34 1016.34,2658.66 v1(1017,2658) ; C187.2@1679,2053.69 1703.69,2053.69 1720.69,2070.69 v1(1738,2070.69) ; v1(2248,86) R131.1@2275.32,86 ; v1(2248,136) R130.1@2275.32,136 ; v1(2248,186) R129.1@2275.32,186 ; v1(2248,236) R128.1@2275.32,236 ; v1(2347,435) 2359.19,447.19 2369.44,447.19 U21.3@2369.5,447.25 ; C55.1@2411,1212 v1(2425,1212) C210.1@2437,1212 ; U21.8@2432.5,478.75 2440.24,478.75 2447.09,485.59 2447.09,493.09 v1(2449,495) 2450.91,496.91 2450.91,503.63 2481,533.72 C111.2@2481,535.69 ; v1(2448.34,994.73) 2448.34,994.47 2461,981.81 C3.1@2461,980.01 2461,978.21 2462.17,977.04 2467.28,977.04 2488.66,955.66 2488.99,955.33 C27.1@2488.99,931 ; C37.2@2553.69,1292 2553.69,1273.35 v1(2563.5,1263.54) ; v1(2615,1238) 2615,1239.41 2634.65,1259.06 C16.2@2634.65,1277.57 ; C54.1@2616.01,1434 2616.27,1434.26 2623.49,1434.26 v1(2623.75,1434.52) 2625.06,1433.21 2625.06,1404.31 C56.2@2626.37,1403 ; C58.2@2666.4,1335.66 2667.23,1334.83 2714.17,1334.83 v1(2715,1334) ; v1(2789.31,2902) 2789.31,2876.69 2794,2872 2841.63,2872 2864.01,2894.38 U51.13@2871.76,2894.38 ; R52.1@2904.47,764.95 2905.23,764.19 2905.23,735.77 v1(2906,735) ; U51.6@2966.24,2925.87 2994.17,2925.87 2997.29,2929 v1(3000,2929) ; R51.1@2969.13,764.95 2970.07,764.02 2970.07,735.93 v1(2971,735) ; U29.3@3086.35,1130.41 3090.09,1126.68 3090.09,1108.91 v1(3092,1107) ; U42.4@3386,2019.91 3386.5,2019.41 3386.5,1974.5 v1(3387,1974) ; C146.2@3579,1988.31 3579.5,1987.81 3579.5,1958.5 v1(3580,1958) ; C145.2@3624,1986.31 3624.5,1985.81 3624.5,1956.5 v1(3625,1956) ; v1(3818,1972) 3818.5,1972.5 3818.5,2017 U40.5@3819,2017.5 ; v1(3905,1973) U43.4@3905,2016.91 ; C147.2@4100,1985.31 4100.5,1984.81 4100.5,1955.5 v1(4101,1955) ; J11.3@4737.2,1135.73 4737.34,1135.87 4805.87,1135.87 v1(4806,1136) ; v1(4927,1709) 4927,1688.41 4928.49,1686.91 J11.60@4962.8,1686.91 5000.51,1686.91 5002,1688.41 v1(5002,1708)
  L08 - BOTTOM w10: v1(1429,330) 1483.95,330 1488.28,325.67 1495.57,325.67 1496.47,324.76 U31.3@1496.47,317.48 1496.47,310.2 1495.57,309.29 1488.28,309.29 1486.52,307.53 1476.53,307.53 v1(1475,306) ; v1(1535.26,977.65) C75_SOM-ETH2.2@1561.45,977.68 ; v1(1535.26,1009.65) 1535.51,1009.91 1561.2,1009.91 C76_SOM-ETH2.2@1561.45,1010.16 ; v1@1535.27,1042.65 C191_SOM-ETH2.2@1561.45,1042.64 ; v1(1536.26,1420.65) C75_SOM-ETH1.2@1562.45,1420.68 ; v1(1536.26,1452.65) 1536.51,1452.91 1562.2,1452.91 C76_SOM-ETH1.2@1562.45,1453.16 ; v1@1536.27,1485.65 1560.48,1485.65 C191_SOM-ETH1.2@1562.45,1485.64 ; v1(1554,1328) 1554.24,1327.76 1554.24,1289.08 U5.3@1554.32,1289 ; v1(1568,301) 1568,303.16 1570.16,305.32 1570.16,325.47 C123.1@1575,330.32 ; v1(1611.13,1588.64) 1611.39,1588.39 1672.88,1588.39 R28_SOM-ETH1.2@1673.13,1588.13 ; v1(1639,1175) 1639.07,1174.93 R25_SOM-ETH2.1@1639.07,1145.45 ; R25_SOM-ETH2.1@1639.13,1145.13 1639.07,1145.2 R25_SOM-ETH2.1@1639.07,1145.45 ; R28_SOM-ETH2.2@1672.13,1145.13 1671.88,1145.39 1639.13,1145.39 R25_SOM-ETH2.1@1639.07,1145.45 ; v1(1693.13,1200.95) R205_SOM-ETH1.2@1789.13,1200.95 R204_SOM-ETH1.2@1822.13,1200.95 ; R205_SOM-ETH2.2@1788.13,757.95 R204_SOM-ETH2.2@1821.13,757.95 1822.16,758.98 1844.98,758.98 v1(1846,760) ; R206_SOM-ETH2.2@1948.1,919.64 1948.46,919.28 1948.46,880.83 C72_SOM-ETH2.2@1948.82,880.47 ; C71_SOM-ETH2.2@1948.82,847.99 C72_SOM-ETH2.2@1948.82,880.47 ; R206_SOM-ETH1.2@1949.1,1362.64 1949.46,1362.28 C72_SOM-ETH1.2@1949.46,1327.78 ; C71_SOM-ETH1.2@1949.82,1290.99 C72_SOM-ETH1.2@1949.82,1323.47 v1(1965.57,1323.47) ; v1(1964.57,880.47) C72_SOM-ETH2.2@1948.82,880.47 ; v1(2128,827) 2156.14,827 2180.7,851.56 2180.7,870.05 2207,896.35 C50.2@2207,898.31 ; R21.1@2332.68,1554.91 2334.65,1554.91 2352.16,1537.4 2352.16,1517.43 v3(2354.02,1515.57) ; C31.1@2407,931 2407.17,930.83 2417.01,930.83 2419.84,928 v1(2422,928) 2423.5,929.5 C201.1@2435.5,929.5 ; C9.1@2538,1137 v1(2551,1137) 2563.83,1137 C190.1@2564,1136.83
  L08 - BOTTOM w12: C109.2@1048.91,522 1050.91,524 v1(1091,524) ; C107.2@1048.91,568 1048.91,567.02 1061.65,554.27 1081.49,554.27 1088.75,547 v1(1092,547) ; C105.2@1048.91,671 1056.91,679.01 1070.14,679.01 v1(1082,690.87) ; C103.2@1048.91,717 1073.75,717 1077.75,713 v1(1081,713) ; C108.2@1048.91,1761 1049.41,1761.5 1077.5,1761.5 v1(1078,1762) ; C106.2@1048.91,1808 1058.18,1798.72 1082.65,1798.72 1088.38,1793 v1(1090,1793) ; C104.2@1048.91,1909 1048.91,1909.98 1058.65,1919.73 1073.11,1919.73 1085.38,1932 v1(1087,1932) ; C102.2@1048.91,1955 1049.41,1955.5 1077.5,1955.5 v1(1078,1956)
  L08 - BOTTOM w15: v1(1625,1717) R191.1@1625,1745 1625.16,1745.16 1657.84,1745.16 R190.1@1658,1745.32 ; C35.2@2336.69,1080 2338.65,1080 2341,1082.34 2341,1091.18 2346.15,1096.34 v1(2346.15,1097.15) ; R197.2@2987.13,1586.29 2987.28,1586.15 3012.85,1586.15 v1(3013,1586) ; J6.6@3244.92,462.92 3244.96,462.96 v1(3245,505) v1(3245,505)
  L08 - BOTTOM w20: v1(2880,1270) R195.2@2904.98,1270
  other v1: 3190.36,33.78 3415,35 3204.59,105 3301.94,105 3399.29,105 3496.65,105 3594,105 1228.76,107.46 1449.24,107.46 1633.76,107.46 1854.24,107.46 778,243 5103,320 778,340.35 2208,347.32 5103,417.35 1557,432.32 1589,432.32 778,437.71 5103,514.71 778,535.06 1202,545.66 1234,572.63 1810.44,605.31 5103,612.06 1027.87,620 778,632.41 1849.81,646.65 1202,668.37 1976.61,676.46 1846.29,691.52 1234,693.37 5103,709.41 778,729.76 5103,806.76 778,827.12 2975.56,887.95 5103,904.12 778,924.47 2358,944 2936.19,966.69 5103,1001.47 2371.85,1020.48 2422.76,1020.53 2474.06,1020.53 4850,1042 1535.26,1042.65 2499.15,1045.48 3054.3,1045.43 2397.18,1045.73 2448.09,1045.61 2371.28,1071.68 2422.83,1071.68 2474.01,1071.51 1602.65,1077 2397.33,1096.77 2448.34,1096.77 2371,1122.73 2422.31,1122.91 2473.44,1122.73 4850,1125 2346.15,1148.48 2448.02,1148.14 1560.61,1171.16 1491.72,1192.12 4850,1193 751.55,1198.68 1490.72,1228.75 873.65,1234 971,1234 1068.35,1234 1165.71,1234 1263.06,1234 751.55,1237.68 3077.13,1256.83 2987.54,1268.05 4850,1276.48 751.55,1277.68 4850,1360 3121,1386 3141,1386 2780.13,1389.39 2462.15,1393.17 2524.15,1398.17 3101,1405 3121,1405 3141,1405 2976.68,1405.95 2999.17,1405.95 2756,1424 2775.2,1424 2813.6,1424 2832.8,1424 2852,1424 3081,1424 3101,1424 3121,1424 3141,1424 2663.39,1434.66 2976.68,1440.6 2999.17,1440.6 4851,1443 1536.26,1485.65 781,1511 2664.68,1564 4850,1574 781,1608.35 4850,1610 781,1705.71 4850,1707 4850,1761 1201,1777.63 781,1803.06 1234,1804.63 2001,1839 1027.87,1853 2016,1887.31 1201,1899.37 781,1900.41 1659.31,1913 1234,1927.37 1949.15,1949.33 1619.63,1992.37 781,1997.76 4187,2036 4217,2036.45 4250,2037 3297,2051 1997.67,2052.33 3225,2052 3261,2052.26 781,2095.12 781,2192.47 4560,2227 4560,2324.35 1952.59,2346 2049.94,2346 2147.29,2346 2244.65,2346 2342,2346 183.59,2408 280.94,2408 378.29,2408 475.65,2408 573,2408 4560,2421.71 4560,2519.06 4560,2616.41 106.46,2655.24 2398.65,2894.81 1169.68,2993.24 5117,2996 2421.68,3047 1927.65,3054.28 2153.65,3055 2591,3065.69 1926.65,3086.28 2151.69,3087 5117,3093.35 1079.68,3101.13 1489,3111 1831,3113 2349,3124.56 2138.67,3136.28 1489,3136.67 1947.33,3137.28 1831,3138.67 1489,3162.33 1831,3164.33 1040,3178 1233,3181 1489,3188 1831,3190 5117,3190.71 1039.15,3213 1231,3218 2086.32,3229.33 1231,3247 1039,3250 1968.32,3274.67 5117,3288.06 1462,3290 1487.67,3290 1539,3290 1787,3290 1838.33,3290 1864,3290 2450,3378.45 5117,3385.41 2947.31,3398.13 3210,3409 3246.32,3409.45 3280,3409 1818.16,3450.65 1507.65,3451.65 1499.04,3492.65 1661.69,3500.21 1742.09,3525.65 1779.76,3525.65 1064,3528.54 1158,3528.54 969,3530.5 2010,3549 2067,3549 2039.32,3550.01
  other v2: 1560.77,547.18 1598.17,547.18 1560.77,584.58 1598.17,584.58 828.42,2483.46 865.82,2483.46 865.82,2520.86 2039,3042.63 2039,3085.94 1662.41,3326.16 1643.12,3357.65 1681.7,3357.65 1662.41,3389.15 1662.41,3433.44
  other v3: 1755.65,917.98 1724.15,949.48 1755.65,949.48 1787.14,949.48 1755.65,980.98 1756.65,1360.98 1725.15,1392.48 1756.65,1392.48 1788.14,1392.48 1756.65,1423.98
GND_XDS: C140.2 C141.2 C142.1 C143.2 C144.1 C148.2 C149.2 C150.2 C151.1 C152.1 C153.2 C154.2 C155.2 C156.2 C157.2 C158.2 C159.2 C160.2 C162.2 C163.2 C164.2 C165.2 C166.2 C167.2 C168.2 C169.2 C170.2 C171.2 D20.1 D21.1 D22.1 J15.5 R148.1 R153.1 R158.1 R159.1 R160.1 R161.1 R162.2 R167.1 R168.1 TP14.1 TP31.1 U40.4 U41.10 U41.17 U41.48 U41.55 U41.58 U41.64 U41.66 U41.80 U41.114 U42.5 U43.5 U44.3@4545,3404.56 U44.8@4545,3437.44 U45.6 U45.9@4462,3259.64 U46.2 Y1.2 Y1.4 | length 1768.8
  L01 - TOP w8: R161.1@3438,2404 3438.5,2404.5 3594.5,2404.5 v1(3595,2405) ; v1(4449,3178) 4449.1,3178.1 4449.1,3204.42 U45.6@4449.2,3204.52 ; J15.5@4506.82,3499.07 4506.91,3499.16 4506.91,3541.91 v1(4507,3542) ; v1(4545,3404.56) v1(4545,3437.44)
  L04 - GND w8: v1(4507,3542) 4538.97,3542 4545,3535.97 v1(4545,3437.44)
  L02 - GND w8: v1(4507,3542) 4538.97,3542 4545,3535.97 v1(4545,3437.44)
  L07 - GND w8: v1(4507,3542) 4538.97,3542 4545,3535.97 v1(4545,3437.44)
  L08 - BOTTOM w8: v1(3217,2649) 3217.35,2649.35 3248.27,2649.35 C167.2@3248.62,2649.7 C152.1@3248.63,2618 ; v1(3348,2611) U41.66@3394.84,2610.98 ; TP14.1@3378,3201 3378,3164 v1(3405,3137) ; U42.5@3386,2236.44 v1(3386,2281) ; U41.80@3394.86,2831.43 U41.80@3394.86,2831.43 3440.64,2831.36 v1(3441,2831) ; v1(3426,2529) 3428.71,2529 3435.86,2536.15 U41.64@3453.92,2536.15 ; U41.58@3548.4,2536.15 3548.47,2536.09 3548.47,2508.5 3559.74,2497.23 3577.07,2497.23 3590.29,2484 v1(3593,2484) 3593,2486.71 3595.65,2489.35 U41.55@3595.65,2536.15 ; v1(3578,2290) 3578.5,2289.5 3578.5,2262.19 C149.2@3579,2261.69 ; C148.2@3624,2259.69 v1(3624,2289) ; C169.2@3681,3274.53 3689.72,3265.81 3718.84,3265.81 v1(3736,3248.65) ; U41.48@3705.88,2536.15 3705.88,2492.82 3709,2489.71 v1(3709,2487) ; v1(3718,3181) 3718,3178.29 3721.57,3174.72 3721.57,3142.51 U41.114@3721.63,3142.45 ; U40.4@3819,2234.5 v1(3819,2277) ; v1(3904,2276) 3904.5,2275.5 3904.5,2233.94 U43.5@3905,2233.44 ; U41.17@4001.16,2831.43 U41.17@4001.16,2831.43 4037.93,2831.36 4050.29,2819 v1(4053,2819) ; U41.10@4001.16,2941.66 4047.96,2941.66 4062.62,2927 v1(4063,2927) ; C150.2@4100,2258.69 v1(4100,2288) ; C157.2@4121.69,2676 v1(4150,2676) ; C155.2@4121.69,2846 4121.84,2846.16 4121.84,2872.84 v1(4122,2873) ; C154.2@4121.69,2979 v1(4151,2979) ; C164.2@4230.69,2874.55 4230.96,2874.27 4265.76,2874.27 v1(4266.03,2874) ; C165.2@4230.69,2909 4230.96,2908.73 4265.76,2908.73 v1(4266.03,2908.45) ; U46.2@4275.24,2745.6 4275.44,2745.8 4313.8,2745.8 v1(4314,2746)
  other v1: 3225,2210 3261,2209.74 3300,2210 4187,2214 4250,2214 4217,2214.8 3844,2415.31 3191.31,2848 3343,2891.31 3307.01,2898.65 3242.51,2921.99 3179.51,3008.61 3306.01,3022.95 4302.5,3025 3342,3043.65 4465.65,3084 4303.5,3092 4377,3202.31 4577,3214.69 4002,3219.37 4036,3219.37 3530,3246.69 4708.67,3303 4377,3322.69 4715,3365.31 4756,3365.33 4218,3414 4250.31,3414 4284,3414 4822,3605 4852.43,3605.77 4880,3606
  other v2: 4462,3237 4424.6,3259.64 4499.4,3259.64 4462,3282.28
HPI_IRQ0: J11.26 U2.T1 | length 2781.5
  L01 - TOP w4.3: U2.T1@2665.86,1212.36 2666.61,1212.36 2690.25,1236 v1(2691,1236) ; v1(4287,1397) 4312.52,1371.48 4650.66,1371.48 4679.29,1342.85 5033.37,1342.85 v1(5043,1352.48)
  L03 - SIG w4.5: v1(2691,1236) 2692.75,1236 2710.9,1254.15 2729.83,1254.15 2825.85,1254.15 2854,1226 3246,1226 3353,1119 4195.36,1119 4198,1121.64 4198,1308 v1(4287,1397)
  L08 - BOTTOM w4.3: J11.26@4962.8,1352.27 4962.9,1352.37 5042.89,1352.37 v1(5043,1352.48)
HPI_IRQ1: J11.27 U2.U1 | length 2360.7
  L01 - TOP w4.3: U2.U1@2665.86,1237.95 2681.91,1254 2701,1254 v1(2718,1237)
  L03 - SIG w4.5: v1(2718,1237) 2729.83,1237 2826,1237 2847.5,1215.5 3241.65,1215.5 3348.65,1108.5 3351.5,1108.5 3353,1107 4214.36,1107 4217,1109.64 4217,1301 v1(4287,1371)
  L08 - BOTTOM w4.5: v1(4287,1371) 4287.48,1371.48 4736.73,1371.48 J11.27@4737.2,1371.95
HPI_IRQ2: J11.28 U2.B10 | length 3545.3
  L01 - TOP w4.5: v1(3916,1357) 4201.77,1357 4259.02,1414.25 4297.35,1414.25 4327.6,1384 4850.4,1384 4862.92,1371.48 v1(5073,1371.48)
  L06 - SIG w4.5: v1(2435.54,854.09) 2463.83,825.81 2476.45,825.81 2503.85,798.4 2503.85,766.84 2590.19,680.5 3897.5,680.5 3916,699 v1(3916,1357)
  L08 - BOTTOM w4.5: J11.28@4962.8,1371.95 4963.03,1371.72 5072.76,1371.72 v1(5073,1371.48)
HPI_IRQ3: J11.49 U2.C19 | length 3843.6
  L01 - TOP w3.5: U2.C19@2205.23,879.69 2206.46,879.69 2230.77,904 v1(2232,904)
  L06 - SIG w4.5: v1(2232,904) 2178.55,850.55 2178.55,838.59 2158,818.04 2158,776.34 2158,719.85 2319.85,558 3013.76,558 3025.51,569.75 3138.49,569.75 3141.49,566.75 3650.49,566.75 3659.24,558 3871.76,558 4033,719.24 v1(4033,1580)
  L08 - BOTTOM w4.5: v1@4033.27,1580 4162,1580 4176.75,1594.75 4645.94,1594.75 4652.2,1588.49 J11.49@4737.2,1588.49
HPI_RESET: J11.58 U47.4 U50.3 U54.2 | length 4682.5
  L01 - TOP w4.3: U47.4@2026.04,598.76 2094.24,598.76 2195.85,497.15 2302.33,497.15 2304.85,494.63 2304.85,492.9 2318.94,478.81 2343.19,478.81 2465,357 v1(2465,333) ; v1(3303,219) 3306.71,219 3311.31,223.6 U50.3@3350.64,223.6 3363.94,223.6 3398.54,189 3539,189 3580,230 3580,441 3621,482 3694,482 3829.22,617.22 3889.71,617.22 ; U54.2@3889.71,595.88 3889.71,617.1 3889.84,617.22 3929.78,617.22 3941,606 v1(3941,588)
  L01 - TOP w4.5: v1(4075,1688) 4076.75,1689.75 5020.69,1689.75 v1(5043,1667.44)
  L03 - SIG w4.5: v1(2465,333) 2539.25,258.75 2701.15,258.75 2725.65,283.25 2777.35,283.25 2804.39,256.21 3265.79,256.21 v1(3303,219)
  L06 - SIG w4.5: v1(3941,588) 4067,714 4067,1435.6 4069.25,1437.85 4069.25,1678.61 4075,1684.36 v1(4075,1688)
  L08 - BOTTOM w4.5: J11.58@4962.8,1667.23 4962.9,1667.33 5042.89,1667.33 v1(5043,1667.44)
LED_DRIVER_EN: R95.2 U22.17 U23.7 | length 313.6
  L03 - SIG w6: v1(724,2654) 784.54,2654 856.54,2582 v1(857,2582)
  L08 - BOTTOM w6: U22.17@625.08,2693.65 702.63,2693.65 708.13,2688.16 708.13,2683.49 721.7,2669.91 721.7,2656.3 v1(724,2654) ; U23.7@856.96,2557.28 v1(857,2582)
M_PR1_PRU0_GPIO0: J11.5 U26.16 | length 995.4
  L01 - TOP w4.5: v1(4245,686) 4245,682.35 4252.38,674.97 U26.16@4252.38,640.24
  L06 - SIG w4.5: v1(4245,686) 4274,715 4274,1152 v1(4272,1154)
  L08 - BOTTOM w4.5: v1(4272,1154) 4272.71,1154.71 4736.5,1154.71 J11.5@4737.2,1155.42
M_PR1_PRU0_GPIO1: J11.6 U26.3 | length 1486.9
  L01 - TOP w4.3: v1(4208,574) 4219.13,585.13 U26.3@4244.5,585.13 ; v1(4253,1103) 4883.97,1103 4932.12,1151.15 5034.44,1151.15 5039.29,1156 v1(5043,1156)
  L06 - SIG w4.5: v1(4208,574) 4218.75,584.75 4222.15,584.75 4232.25,594.85 4232.25,609.15 4227.75,613.65 4227.75,693.15 4246,711.4 4246,1093.61 4253,1100.61 v1(4253,1103)
  L08 - BOTTOM w4.3: J11.6@4962.8,1155.42 4963.09,1155.71 5042.71,1155.71 v1(5043,1156)
M_PR1_PRU0_GPIO9: J11.14 U26.9 | length 1402.7
  L01 - TOP w4.5: U26.9@4307.5,569.38 4315.37,569.38 4325.42,559.33 4325.42,550.58 v1(4328,548) ; v1@4532,1234 4532.37,1234.37 v1(5043,1234.37)
  L06 - SIG w4.5: v1(4328,548) 4355.75,575.75 4355.75,660.14 4365.85,670.25 4376.01,670.25 4532,826.24 v1(4532,1234.37)
  L08 - BOTTOM w4.5: J11.14@4962.8,1234.16 4962.9,1234.26 5042.89,1234.26 v1(5043,1234.37)
M_PR1_PRU1_GPIO3: J11.32 U27.16 | length 1443.6
  L01 - TOP w4.3: v1(4417,672) 4418.49,672 4430.19,660.3 4430.19,641.43 U27.16@4431.38,640.24 ; v1(4593,1412.86) 4594,1411.85 5072,1411.85 v1(5073,1410.85)
  L06 - SIG w4.5: v1(4417,672) 4593,848 v1(4593,1412.86)
  L08 - BOTTOM w4.3: J11.32@4962.8,1411.32 4963.03,1411.09 5072.76,1411.09 v1(5073,1410.85)
M_PR1_PRU1_GPIO14: J11.43 U28.16 | length 1700.8
  L01 - TOP w4.5: v1(3998,534) 4009.38,522.62 U28.16@4009.38,505.24
  L06 - SIG w4.5: v1(3998,534) 4138,674 v1(4138,1528)
  L08 - BOTTOM w4.5: v1(4138,1528) 4305.6,1528 4325.85,1548.25 4565.15,1548.25 4583.96,1529.43 J11.43@4737.2,1529.43
M_PR1_PRU1_GPIO15: J11.44 U27.3 | length 1696.1
  L01 - TOP w4.3: v1(4392,577) 4395.71,577 4403.83,585.13 U27.3@4423.5,585.13 ; v1(4560,1529) v1(5073,1528.96)
  L06 - SIG w4.5: v1(4392,577) 4372.43,596.57 4372.43,628.03 4390.25,645.85 4390.25,669.64 4560,839.39 v1(4560,1529)
  L08 - BOTTOM w4.3: J11.44@4962.8,1529.43 4963.03,1529.2 5072.76,1529.2 v1(5073,1528.96)
M_PR1_PRU1_GPIO16: J11.45 U27.9 | length 1220.8
  L01 - TOP w4.3: U27.9@4486.5,569.38 4505.62,569.38 v1(4519,556)
  L06 - SIG w4.5: v1(4519,556) 4610,647 4610,1405.46 4610.25,1405.71 4610.25,1566.25 v1(4611,1567)
  L08 - BOTTOM w4.5: v1(4611,1567) 4628.88,1549.12 J11.45@4737.2,1549.12
M_PR1_PRU1_GPIO17: J11.46 U28.3 | length 2182
  L01 - TOP w4.5: v1(3970,444) 3972.71,444 3978.83,450.13 U28.3@4001.5,450.13 ; v1(4159,1549) 4159.33,1549.33 v1(5043,1549.33)
  L06 - SIG w4.5: v1(3970,444) 3970.4,444 4027.06,500.67 4027.06,546.15 4037.17,556.25 4037.25,556.25 4159,678 v1(4159,1549)
  L08 - BOTTOM w4.5: J11.46@4962.8,1549.12 4962.9,1549.22 5042.89,1549.22 v1(5043,1549.33)
M_PR1_PRU1_GPIO18: J11.47 U28.9 | length 1850.3
  L01 - TOP w4.5: U28.9@4064.5,434.38 4082.23,434.38 4100.6,416 v1(4101,416)
  L06 - SIG w4.5: v1(4101,416) 4100.6,416 4059.75,456.85 4059.75,530.04 4171,641.29 4171,1536.6 4176.25,1541.85 4176.25,1558.61 4184,1566.36 v1(4184,1568)
  L08 - BOTTOM w4.5: v1(4184,1568) 4184,1566.6 4204.6,1546 4292,1546 4330.25,1584.25 4641.59,1584.25 4657.04,1568.8 J11.47@4737.2,1568.8
M_PR1_PRU1_GPIO19: J11.48 U28.12 | length 2173.3
  L01 - TOP w4.5: U28.12@4064.5,481.62 4065.69,482.81 4095.81,482.81 v1(4097,484) ; v1(4208,1567) 4232.25,1591.25 5045.75,1591.25 v1(5074,1563)
  L06 - SIG w4.5: v1(4097,484) 4152,539 4152,593.09 4196.25,637.34 4196.25,706.19 4214.5,724.44 4214.5,1150.59 4219.5,1155.59 4219.5,1555.5 v1(4208,1567)
  L08 - BOTTOM w4.5: J11.48@4962.8,1568.8 4963.03,1568.57 5056,1568.57 5058.98,1565.58 5071.42,1565.58 v1(5074,1563)
MDC_SOM-ETH1: R233_SOM-ETH1.2 R233_SOM-ETH2.2 U5.6 U9_SOM-ETH1.12 U9_SOM-ETH2.12 | length 811.2
  L01 - TOP w4.3: v1(1746,887) 1745.9,886.9 1745.9,855.09 U9_SOM-ETH2.12@1745.8,854.99 1745.8,809.62 1756.13,799.29 R233_SOM-ETH2.2@1756.13,797.32 ; v1(1746,1329) 1746.4,1328.6 1746.4,1298.39 U9_SOM-ETH1.12@1746.8,1297.99 1746.8,1252.62 1757.13,1242.29 R233_SOM-ETH1.2@1757.13,1240.32
  L03 - SIG w4.5: v1(1613,1108) 1638.91,1108 1710.38,1179.48 1710.38,1293.38 v1(1746,1329)
  L06 - SIG w4.5: v1(1613,1108) 1599.78,1094.78 1596.04,1094.78 1585.4,1084.15 1585.4,1049.76 1746,889.17 v1(1746,887)
  L08 - BOTTOM w4.3: U5.6@1593.69,1121.68 1593.69,1110.56 1596.25,1108 v1(1613,1108)
MDIO/MDC_MUX_SEL: U5.1 U5.5 U7.5 | length 1006.7
  L01 - TOP w4.5: U7.5@1609,621 1609,643.35 1617,651.35 v1(1617,655)
  L06 - SIG w4.5: v1(1494,1305) 1462,1273 1462,969 1617,814 v1(1617,655)
  L08 - BOTTOM w4.3: U5.1@1514.94,1289 1514.94,1291.51 1512.38,1294.08 1504.92,1294.08 v1(1494,1305) 1494,1329.53 1515,1350.53 1583.72,1350.53 1615,1319.25 1615,1299 1605,1289 U5.5@1593.69,1289
MDIO_SOM-ETH1: R23_SOM-ETH1.2 R23_SOM-ETH2.2 U5.10 U9_SOM-ETH1.11 U9_SOM-ETH2.11 | length 898.9
  L01 - TOP w4.3: v1(1709,1329) 1720.5,1317.5 1720.5,1311.5 1727.12,1304.88 1727.12,1242.31 R23_SOM-ETH1.2@1725.13,1240.32 ; R23_SOM-ETH2.2@1724.13,797.32 v1(1724.76,797.95) 1726.12,799.31 U9_SOM-ETH2.11@1726.12,854.99
  L03 - SIG w4.5: v1(1496,1121) 1530.61,1155.61 1530.61,1168.01 1691.6,1329 v1(1709,1329)
  L06 - SIG w4.5: v1(1496,1121) 1497.06,1119.94 1497.06,1105.25 1552.51,1049.8 1552.51,1033.87 1724.76,861.62 v1(1724.76,797.95)
  L08 - BOTTOM w6: v1(1496,1121) 1514.27,1121 U5.10@1514.94,1121.68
